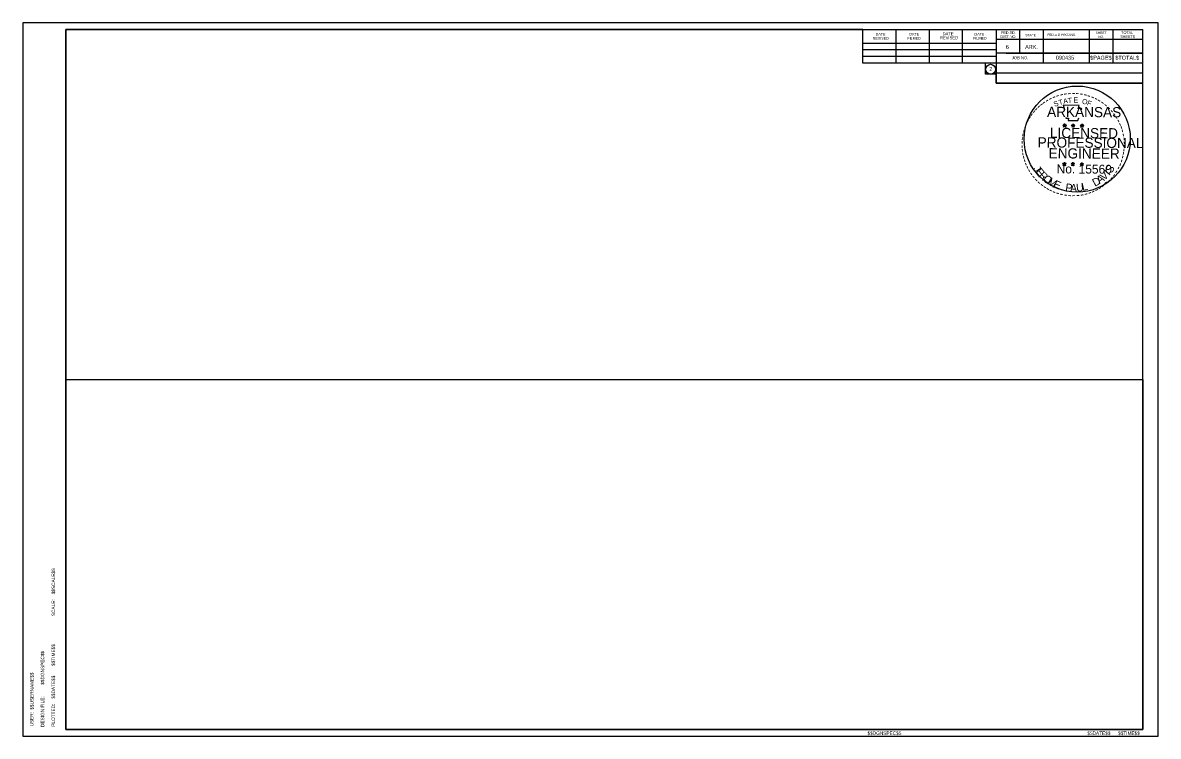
# Model space of a CAD drawing. Extents: x -1.3 to 32.1, y -0.2 to 20.7.
import ezdxf

# ---------------------------------------------------------------- set-up
doc = ezdxf.new("R2010")
doc.units = 0
for name, color, linetype in [('Level 24', 7, 'Continuous'), ('Level 37', 7, 'Continuous'), ('Level 49', 7, 'Continuous'), ('Level 62', 7, 'Continuous'), ('Level 63', 7, 'Continuous'), ('R_Border', 7, 'Continuous'), ('R_Border Notes', 7, 'Continuous'), ('Stamp Mask', 7, 'Continuous')]:
    doc.layers.add(name, color=color, linetype=linetype)

msp = doc.modelspace()

# ---------------------------------------------------------------- linework, layer by layer
at = {"layer": 'Level 24'}
for p, q in [((-0.001, 20.545), (-0.001, -0.001)), ((23.391, 19.557), (23.391, 20.545)), ((26.999, 19.557), (23.391, 19.557)), ((26.999, 19.232), (26.999, 19.557)), ((27.307, 19.233), (26.999, 19.232)), ((27.307, 18.973), (27.307, 19.233)), ((31.617, 18.973), (27.307, 18.973)), ((31.617, -0.001), (31.617, 18.973)), ((-0.001, -0.001), (31.617, -0.001))]:
    msp.add_line(p, q, dxfattribs=at)
msp.add_lwpolyline([(23.391, 20.545), (23.391, 20.545), (23.391, 20.545), (-0.001, 20.545)], dxfattribs=at)
at = {"layer": 'Level 37'}
for p, q in [((-0.002, 0.481), (-0.001, 10.271)), ((-0.001, 10.271), (31.617, 10.271)), ((31.617, 10.271), (31.617, -0.001)), ((-0.001, -0.001), (-0.002, 0.481)), ((-0.002, 0.481), (-0.002, 0.481)), ((31.617, -0.001), (-0.001, -0.001))]:
    msp.add_line(p, q, dxfattribs=at)
at = {"layer": 'Level 49'}
for p, q in [((29.266, 17.742), (29.319, 17.726)), ((29.266, 17.742), (29.304, 17.74)), ((29.266, 17.742), (29.304, 17.739)), ((29.266, 17.742), (29.301, 17.733)), ((29.266, 17.742), (29.301, 17.727)), ((29.266, 17.742), (29.301, 17.726)), ((29.266, 17.742), (29.301, 17.72)), ((29.288, 17.681), (29.319, 17.726)), ((29.288, 17.681), (29.301, 17.724)), ((29.288, 17.681), (29.304, 17.718)), ((29.288, 17.681), (29.306, 17.716)), ((29.288, 17.681), (29.312, 17.713)), ((29.288, 17.681), (29.319, 17.713)), ((29.288, 17.681), (29.319, 17.709)), ((29.319, 17.783), (29.312, 17.742)), ((29.319, 17.783), (29.312, 17.746)), ((29.319, 17.783), (29.315, 17.746)), ((29.319, 17.726), (29.319, 17.783)), ((29.319, 17.783), (29.328, 17.742)), ((29.319, 17.783), (29.326, 17.746)), ((29.319, 17.783), (29.321, 17.746)), ((29.371, 17.742), (29.319, 17.726)), ((29.35, 17.68), (29.319, 17.726)), ((29.35, 17.68), (29.319, 17.713)), ((29.35, 17.68), (29.319, 17.709)), ((29.371, 17.742), (29.323, 17.739)), ((29.35, 17.68), (29.323, 17.713)), ((29.371, 17.742), (29.328, 17.735)), ((29.371, 17.742), (29.328, 17.731)), ((29.35, 17.68), (29.328, 17.724)), ((29.35, 17.68), (29.328, 17.718)), ((29.35, 17.68), (29.334, 17.726)), ((29.371, 17.742), (29.336, 17.731)), ((29.371, 17.742), (29.341, 17.727)), ((29.371, 17.742), (29.343, 17.726)), ((29.514, 17.74), (29.568, 17.726)), ((29.514, 17.74), (29.553, 17.739)), ((29.514, 17.74), (29.553, 17.735)), ((29.514, 17.74), (29.553, 17.733)), ((29.514, 17.74), (29.551, 17.726)), ((29.514, 17.74), (29.551, 17.724)), ((29.514, 17.74), (29.551, 17.718)), ((29.536, 17.68), (29.568, 17.726)), ((29.536, 17.68), (29.553, 17.72)), ((29.536, 17.68), (29.553, 17.718)), ((29.536, 17.68), (29.555, 17.716)), ((29.536, 17.68), (29.56, 17.711)), ((29.536, 17.68), (29.568, 17.711)), ((29.536, 17.68), (29.568, 17.709)), ((29.568, 17.779), (29.56, 17.74)), ((29.568, 17.779), (29.56, 17.742)), ((29.568, 17.779), (29.562, 17.742)), ((29.568, 17.726), (29.568, 17.779)), ((29.568, 17.779), (29.577, 17.74)), ((29.568, 17.779), (29.575, 17.742)), ((29.568, 17.779), (29.57, 17.742)), ((29.619, 17.74), (29.568, 17.726)), ((29.599, 17.68), (29.568, 17.726)), ((29.599, 17.68), (29.568, 17.711)), ((29.599, 17.68), (29.568, 17.709)), ((29.619, 17.74), (29.573, 17.739)), ((29.599, 17.68), (29.573, 17.711)), ((29.619, 17.74), (29.577, 17.733)), ((29.619, 17.74), (29.577, 17.731)), ((29.599, 17.68), (29.577, 17.724)), ((29.599, 17.68), (29.577, 17.716)), ((29.599, 17.68), (29.583, 17.724)), ((29.619, 17.74), (29.584, 17.727)), ((29.619, 17.74), (29.59, 17.726)), ((29.619, 17.74), (29.592, 17.724)), ((29.778, 17.739), (29.831, 17.72)), ((29.778, 17.739), (29.82, 17.733)), ((29.778, 17.739), (29.816, 17.731)), ((29.778, 17.739), (29.816, 17.727)), ((29.778, 17.739), (29.815, 17.724)), ((29.778, 17.739), (29.815, 17.718)), ((29.778, 17.739), (29.815, 17.718)), ((29.798, 17.678), (29.831, 17.72)), ((29.798, 17.678), (29.816, 17.718)), ((29.798, 17.678), (29.82, 17.713)), ((29.798, 17.678), (29.82, 17.711)), ((29.798, 17.678), (29.831, 17.711)), ((29.798, 17.678), (29.828, 17.709)), ((29.798, 17.678), (29.835, 17.704)), ((29.831, 17.775), (29.822, 17.74)), ((29.831, 17.775), (29.828, 17.739)), ((29.831, 17.775), (29.828, 17.739)), ((29.831, 17.72), (29.831, 17.775)), ((29.831, 17.775), (29.842, 17.739)), ((29.831, 17.775), (29.839, 17.739)), ((29.831, 17.775), (29.835, 17.739)), ((29.883, 17.739), (29.831, 17.72)), ((29.861, 17.678), (29.831, 17.72)), ((29.861, 17.678), (29.831, 17.711)), ((29.861, 17.678), (29.831, 17.704)), ((29.883, 17.739), (29.837, 17.733)), ((29.861, 17.678), (29.837, 17.709)), ((29.883, 17.739), (29.842, 17.731)), ((29.883, 17.739), (29.842, 17.726)), ((29.861, 17.678), (29.842, 17.718)), ((29.861, 17.678), (29.842, 17.713)), ((29.861, 17.678), (29.846, 17.718)), ((29.883, 17.739), (29.85, 17.724)), ((29.883, 17.739), (29.851, 17.724)), ((29.883, 17.739), (29.857, 17.72)), ((29.258, 16.611), (29.312, 16.595)), ((29.258, 16.611), (29.297, 16.609)), ((29.258, 16.611), (29.295, 16.604)), ((29.258, 16.611), (29.295, 16.604)), ((29.258, 16.611), (29.295, 16.596)), ((29.258, 16.611), (29.295, 16.595)), ((29.258, 16.611), (29.295, 16.593)), ((29.277, 16.554), (29.312, 16.595)), ((29.277, 16.554), (29.295, 16.595)), ((29.277, 16.554), (29.297, 16.587)), ((29.277, 16.554), (29.299, 16.587)), ((29.277, 16.554), (29.312, 16.585)), ((29.277, 16.554), (29.304, 16.582)), ((29.277, 16.554), (29.312, 16.58)), ((29.312, 16.652), (29.301, 16.615)), ((29.312, 16.652), (29.304, 16.611)), ((29.312, 16.652), (29.306, 16.611)), ((29.341, 16.55), (29.308, 16.58)), ((29.312, 16.595), (29.312, 16.652)), ((29.312, 16.652), (29.319, 16.611)), ((29.312, 16.652), (29.319, 16.611)), ((29.312, 16.652), (29.312, 16.611)), ((29.363, 16.611), (29.312, 16.595)), ((29.341, 16.55), (29.312, 16.595)), ((29.341, 16.55), (29.312, 16.582)), ((29.341, 16.55), (29.314, 16.582)), ((29.363, 16.611), (29.315, 16.609)), ((29.363, 16.611), (29.319, 16.604)), ((29.363, 16.611), (29.319, 16.602)), ((29.341, 16.55), (29.319, 16.595)), ((29.341, 16.55), (29.319, 16.587)), ((29.363, 16.611), (29.326, 16.6)), ((29.341, 16.55), (29.326, 16.595)), ((29.363, 16.611), (29.33, 16.596)), ((29.363, 16.611), (29.334, 16.595)), ((29.507, 16.611), (29.56, 16.595)), ((29.507, 16.611), (29.546, 16.608)), ((29.507, 16.611), (29.546, 16.604)), ((29.507, 16.611), (29.546, 16.602)), ((29.507, 16.611), (29.544, 16.596)), ((29.507, 16.611), (29.544, 16.593)), ((29.507, 16.611), (29.544, 16.589)), ((29.525, 16.55), (29.56, 16.595)), ((29.525, 16.55), (29.546, 16.593)), ((29.525, 16.55), (29.546, 16.585)), ((29.525, 16.55), (29.548, 16.585)), ((29.525, 16.55), (29.553, 16.582)), ((29.525, 16.55), (29.56, 16.582)), ((29.525, 16.55), (29.56, 16.578)), ((29.56, 16.648), (29.551, 16.611)), ((29.56, 16.648), (29.553, 16.611)), ((29.56, 16.648), (29.555, 16.611)), ((29.59, 16.55), (29.559, 16.578)), ((29.56, 16.595), (29.56, 16.648)), ((29.56, 16.648), (29.568, 16.609)), ((29.56, 16.648), (29.568, 16.609)), ((29.56, 16.648), (29.56, 16.611)), ((29.61, 16.609), (29.56, 16.595)), ((29.59, 16.55), (29.56, 16.595)), ((29.59, 16.55), (29.56, 16.582)), ((29.59, 16.55), (29.562, 16.582)), ((29.61, 16.609), (29.566, 16.609)), ((29.61, 16.609), (29.568, 16.602)), ((29.61, 16.609), (29.568, 16.602)), ((29.59, 16.55), (29.568, 16.593)), ((29.59, 16.55), (29.568, 16.587)), ((29.61, 16.609), (29.575, 16.596)), ((29.59, 16.55), (29.575, 16.593)), ((29.61, 16.609), (29.581, 16.595)), ((29.61, 16.609), (29.583, 16.593)), ((29.77, 16.608), (29.824, 16.589)), ((29.77, 16.608), (29.809, 16.604)), ((29.77, 16.608), (29.809, 16.6)), ((29.77, 16.608), (29.807, 16.596)), ((29.77, 16.608), (29.807, 16.593)), ((29.77, 16.608), (29.805, 16.589)), ((29.77, 16.608), (29.805, 16.585)), ((29.791, 16.547), (29.824, 16.589)), ((29.791, 16.547), (29.807, 16.589)), ((29.791, 16.547), (29.809, 16.582)), ((29.791, 16.547), (29.813, 16.582)), ((29.791, 16.547), (29.816, 16.578)), ((29.791, 16.547), (29.822, 16.578)), ((29.791, 16.547), (29.824, 16.574)), ((29.824, 16.646), (29.815, 16.608)), ((29.824, 16.646), (29.816, 16.608)), ((29.824, 16.646), (29.82, 16.608)), ((29.853, 16.547), (29.822, 16.578)), ((29.853, 16.547), (29.822, 16.574)), ((29.824, 16.589), (29.824, 16.646)), ((29.824, 16.646), (29.831, 16.608)), ((29.824, 16.646), (29.831, 16.608)), ((29.824, 16.646), (29.824, 16.608)), ((29.875, 16.608), (29.824, 16.589)), ((29.853, 16.547), (29.824, 16.589)), ((29.853, 16.547), (29.828, 16.578)), ((29.875, 16.608), (29.829, 16.604)), ((29.875, 16.608), (29.831, 16.6)), ((29.875, 16.608), (29.831, 16.596)), ((29.853, 16.547), (29.831, 16.582)), ((29.853, 16.547), (29.835, 16.589)), ((29.853, 16.547), (29.837, 16.589)), ((29.875, 16.608), (29.842, 16.595)), ((29.875, 16.608), (29.844, 16.589)), ((29.875, 16.608), (29.846, 16.589))]:
    msp.add_line(p, q, dxfattribs=at)
for points in [[(29.277, 18.322), (29.314, 18.197)], [(29.8, 18.181), (29.822, 18.225), (29.717, 18.219), (29.741, 18.319), (29.277, 18.322)], [(29.319, 17.783), (29.35, 17.68), (29.266, 17.742), (29.371, 17.742), (29.288, 17.681), (29.319, 17.783)], [(29.349, 17.96), (29.349, 17.945), (29.431, 17.943), (29.424, 17.875), (29.702, 17.873), (29.732, 17.95)], [(29.568, 17.779), (29.599, 17.68), (29.514, 17.74), (29.619, 17.74), (29.536, 17.68), (29.568, 17.779)], [(29.831, 17.775), (29.861, 17.678), (29.778, 17.739), (29.883, 17.739), (29.798, 17.678), (29.831, 17.775)], [(29.312, 16.652), (29.341, 16.55), (29.258, 16.611), (29.363, 16.611), (29.277, 16.554), (29.312, 16.652)], [(29.56, 16.648), (29.59, 16.55), (29.507, 16.611), (29.61, 16.609), (29.525, 16.55), (29.56, 16.648)], [(29.824, 16.646), (29.853, 16.547), (29.77, 16.608), (29.875, 16.608), (29.791, 16.547), (29.824, 16.646)], [(30.515, 16.009), (30.507, 16.033), (30.551, 16.07)], [(30.548, 16.075), (30.555, 16.053), (30.511, 16.014)], [(30.555, 16.057), (30.511, 16.018)], [(30.555, 16.053), (30.513, 16.016)]]:
    msp.add_lwpolyline(points, dxfattribs=at)
for centre, radius in [((29.32, 17.725), 0.0257), ((29.32, 17.725), 0.0233), ((29.32, 17.725), 0.0216), ((29.32, 17.725), 0.0198), ((29.32, 17.725), 0.0173), ((29.32, 17.725), 0.016), ((29.32, 17.725), 0.0148), ((29.32, 17.725), 0.0127), ((29.32, 17.725), 0.0112), ((29.32, 17.725), 0.00927), ((29.32, 17.725), 0.00739), ((29.32, 17.725), 0.00551), ((29.32, 17.725), 0.00442), ((29.32, 17.725), 0.00215), ((29.569, 17.723), 0.0257), ((29.569, 17.723), 0.0233), ((29.569, 17.723), 0.0216), ((29.569, 17.723), 0.0198), ((29.569, 17.723), 0.0173), ((29.569, 17.723), 0.016), ((29.569, 17.723), 0.0148), ((29.569, 17.723), 0.0127), ((29.569, 17.723), 0.0112), ((29.569, 17.723), 0.00927), ((29.569, 17.723), 0.00739), ((29.569, 17.723), 0.00551), ((29.569, 17.723), 0.00442), ((29.569, 17.723), 0.00215), ((29.833, 17.719), 0.0257), ((29.833, 17.719), 0.0233), ((29.833, 17.719), 0.0216), ((29.833, 17.719), 0.0198), ((29.833, 17.719), 0.0173), ((29.833, 17.719), 0.016), ((29.833, 17.719), 0.0148), ((29.833, 17.719), 0.0127), ((29.833, 17.719), 0.0112), ((29.833, 17.719), 0.00927), ((29.833, 17.719), 0.00739), ((29.833, 17.719), 0.00551), ((29.833, 17.719), 0.00442), ((29.833, 17.719), 0.00215), ((29.312, 16.595), 0.0257), ((29.312, 16.595), 0.0233), ((29.312, 16.595), 0.0216), ((29.312, 16.595), 0.0198), ((29.312, 16.595), 0.0173), ((29.312, 16.595), 0.016), ((29.312, 16.595), 0.0148), ((29.312, 16.595), 0.0127), ((29.312, 16.595), 0.0112), ((29.312, 16.595), 0.00927), ((29.312, 16.595), 0.00739), ((29.312, 16.595), 0.00551), ((29.312, 16.595), 0.00442), ((29.312, 16.595), 0.00215), ((29.561, 16.593), 0.0257), ((29.561, 16.593), 0.0233), ((29.561, 16.593), 0.0216), ((29.561, 16.593), 0.0198), ((29.561, 16.593), 0.0173), ((29.561, 16.593), 0.016), ((29.561, 16.593), 0.0148), ((29.561, 16.593), 0.0127), ((29.561, 16.593), 0.0112), ((29.561, 16.593), 0.00927), ((29.561, 16.593), 0.00739), ((29.561, 16.593), 0.00551), ((29.561, 16.593), 0.00442), ((29.561, 16.593), 0.00215), ((29.824, 16.589), 0.0257), ((29.824, 16.589), 0.0233), ((29.824, 16.589), 0.0216), ((29.824, 16.589), 0.0198), ((29.824, 16.589), 0.0173), ((29.824, 16.589), 0.016), ((29.824, 16.589), 0.0148), ((29.824, 16.589), 0.0127), ((29.824, 16.589), 0.0112), ((29.824, 16.589), 0.00927), ((29.824, 16.589), 0.00739), ((29.824, 16.589), 0.00551), ((29.824, 16.589), 0.00442), ((29.824, 16.589), 0.00215)]:
    msp.add_circle(centre, radius, dxfattribs=at)
at = {"layer": 'Level 62'}
msp.add_lwpolyline([(-0.001, -0.001), (31.617, -0.001), (31.617, 19.265), (27.307, 19.265), (27.211, 19.232), (26.999, 19.232), (26.999, 19.557), (23.391, 19.557), (23.391, 20.545), (23.391, 20.545), (23.391, 20.545), (-0.001, 20.545)], close=True, dxfattribs=at)
at = {"layer": 'Level 63'}
msp.add_lwpolyline([(-1.263, -0.2), (32.067, -0.2), (32.067, 20.746), (-1.263, 20.746)], close=True, dxfattribs=at)
at = {"layer": 'R_Border'}
for p, q in [((-0.001, 20.545), (31.617, 20.545)), ((-0.001, -0.001), (-0.001, 20.545)), ((23.391, 19.557), (23.391, 20.545)), ((24.377, 19.557), (24.377, 20.525)), ((25.353, 19.557), (25.353, 20.525)), ((26.321, 19.557), (26.321, 20.525)), ((27.307, 20.545), (27.307, 18.973)), ((27.991, 20.545), (27.991, 19.851)), ((28.685, 20.545), (28.685, 19.557)), ((30.043, 20.545), (30.043, 19.557)), ((30.737, 20.545), (30.737, 19.557)), ((31.617, -0.001), (31.617, 20.545)), ((23.391, 20.143), (27.307, 20.143)), ((31.617, 20.251), (27.307, 20.251)), ((31.617, 20.253), (31.617, 20.253)), ((23.391, 19.957), (27.307, 19.957)), ((23.391, 19.557), (23.391, 19.763)), ((23.391, 19.763), (27.307, 19.763)), ((31.617, 19.851), (27.307, 19.851)), ((27.603, 19.851), (31.617, 19.851)), ((31.617, 19.557), (23.391, 19.557)), ((27.307, 18.973), (31.617, 18.973)), ((31.617, -0.001), (-0.001, -0.001))]:
    msp.add_line(p, q, dxfattribs=at)
msp.add_circle((27.146, 19.379), 0.147, dxfattribs=at)
at = {"layer": 'Stamp Mask'}
msp.add_circle((29.689, 17.331), 1.557, dxfattribs=at)

# ---------------------------------------------------------------- texts
at = {"layer": 'Level 49'}
for s, height, rotation, p in [('-', 0.239, 9.8217, (29.301, 18.553)), ('-', 0.239, 5.4992, (29.411, 18.567)), ('-', 0.239, 359.7886, (29.525, 18.578)), ('-', 0.239, 357.3454, (29.636, 18.575)), ('-', 0.239, 351.7641, (29.745, 18.566)), ('-', 0.239, 38.5531, (28.652, 18.238)), ('-', 0.239, 35.8341, (28.722, 18.295)), ('-', 0.239, 33.666, (28.809, 18.354)), ('-', 0.239, 28.3942, (28.899, 18.407)), ('-', 0.239, 23.9096, (28.993, 18.453)), ('S', 0.149, 21.1964, (29.028, 18.276)), ('-', 0.239, 18.7785, (29.089, 18.494)), ('T', 0.149, 16.006, (29.164, 18.326)), ('-', 0.239, 13.2326, (29.201, 18.529)), ('A', 0.149, 10.8156, (29.29, 18.363)), ('T', 0.149, 5.6252, (29.417, 18.387)), ('E', 0.149, 0.4347, (29.581, 18.402)), ('O', 0.149, 350.0539, (29.82, 18.37)), ('-', 0.239, 346.8073, (29.853, 18.549)), ('F', 0.149, 339.6731, (29.962, 18.333)), ('-', 0.239, 341.9386, (29.947, 18.523)), ('-', 0.239, 337.4575, (30.056, 18.49)), ('-', 0.239, 333.7235, (30.152, 18.451)), ('-', 0.239, 329.2433, (30.236, 18.407)), ('-', 0.239, 325.4651, (30.332, 18.35)), ('-', 0.239, 320.1321, (30.422, 18.287)), ('-', 0.239, 57.673, (28.347, 17.869)), ('-', 0.239, 53.8349, (28.394, 17.95)), ('-', 0.239, 50.2166, (28.457, 18.035)), ('-', 0.239, 48.0254, (28.518, 18.107)), ('-', 0.239, 42.5646, (28.586, 18.177)), ('ARKANSAS', 0.2985, 359.6024, (28.803, 17.983)), ('-', 0.239, 315.181, (30.513, 18.214)), ('-', 0.239, 309.4821, (30.596, 18.131)), ('-', 0.239, 306.2546, (30.671, 18.041)), ('-', 0.239, 71.9969, (28.227, 17.595)), ('-', 0.239, 67.3767, (28.262, 17.689)), ('-', 0.239, 62.4738, (28.3, 17.779)), ('LICENSED', 0.2985, 359.6024, (28.887, 17.365)), ('-', 0.209, 303.2777, (30.745, 17.954)), ('-', 0.239, 299.2708, (30.791, 17.864)), ('-', 0.239, 294.2652, (30.839, 17.772)), ('-', 0.239, 290.1752, (30.879, 17.689)), ('-', 0.239, 84.7887, (28.164, 17.28)), ('-', 0.239, 80.8037, (28.175, 17.383)), ('-', 0.239, 75.0634, (28.197, 17.488)), ('PROFESSIONAL', 0.29847, 359.6024, (28.525, 17.085)), ('-', 0.239, 284.7257, (30.911, 17.6)), ('-', 0.239, 280.1517, (30.94, 17.488)), ('-', 0.239, 276.1986, (30.966, 17.374)), ('-', 0.239, 93.7983, (28.164, 17.066)), ('-', 0.239, 88.6646, (28.16, 17.175)), ('-', 0.239, 98.5503, (28.175, 16.965)), ('ENGINEER', 0.2985, 359.6024, (28.848, 16.766)), ('-', 0.239, 263.1196, (30.973, 17.074)), ('-', 0.239, 273.9325, (30.973, 17.265)), ('-', 0.239, 269.5431, (30.977, 17.173)), ('-', 0.239, 101.3173, (28.192, 16.856)), ('-', 0.239, 105.0602, (28.218, 16.768)), ('-', 0.239, 108.6898, (28.249, 16.676)), ('-', 0.239, 252.4705, (30.918, 16.766)), ('-', 0.239, 255.365, (30.944, 16.875)), ('-', 0.239, 260.5977, (30.96, 16.976)), ('-', 0.239, 113.6667, (28.286, 16.584)), ('-', 0.239, 115.3313, (28.332, 16.491)), ('-', 0.239, 120.0495, (28.383, 16.403)), ('-', 0.239, 125.4958, (28.444, 16.32)), ('J', 0.23, 303.9209, (28.377, 16.456)), ('E', 0.23, 308.618, (28.442, 16.36)), ('R', 0.23, 314.7784, (28.538, 16.242)), ('No. 15560', 0.2626, 359.6024, (29.083, 16.324)), ('V', 0.23, 41.4844, (30.475, 16.1)), ('I', 0.23, 49.9999, (30.628, 16.244)), ('S', 0.23, 53.5227, (30.684, 16.31)), ('-', 0.239, 238.6736, (30.784, 16.462)), ('-', 0.239, 244.2221, (30.842, 16.573)), ('-', 0.239, 247.4911, (30.885, 16.665)), ('-', 0.239, 130.3205, (28.51, 16.237)), ('-', 0.239, 133.8262, (28.588, 16.156)), ('-', 0.239, 138.5362, (28.663, 16.086)), ('-', 0.239, 144.2487, (28.75, 16.025)), ('O', 0.23, 321.6761, (28.66, 16.124)), ('M', 0.23, 328.1357, (28.787, 16.027)), ('E', 0.23, 336.4966, (28.966, 15.924)), ('P', 0.23, 351.9783, (29.328, 15.805)), ('A', 0.23, 357.9896, (29.475, 15.786)), ('U', 0.23, 5.7635, (29.666, 15.785)), ('L', 0.23, 13.0992, (29.846, 15.807)), ('D', 0.23, 28.5809, (30.207, 15.928)), ('A', 0.23, 34.8903, (30.343, 16.004)), ('-', 0.239, 225.3677, (30.586, 16.197)), ('-', 0.239, 233.4476, (30.656, 16.283)), ('-', 0.239, 233.4476, (30.726, 16.364)), ('-', 0.239, 147.6922, (28.831, 15.968)), ('-', 0.239, 151.1728, (28.916, 15.92)), ('-', 0.239, 154.2026, (28.997, 15.882)), ('-', 0.239, 158.1636, (29.089, 15.841)), ('-', 0.239, 162.4007, (29.192, 15.81)), ('-', 0.239, 167.1579, (29.297, 15.786)), ('-', 0.239, 172.7179, (29.411, 15.769)), ('-', 0.239, 176.1207, (29.524, 15.758)), ('-', 0.239, 181.1942, (29.634, 15.762)), ('-', 0.239, 185.4191, (29.756, 15.771)), ('-', 0.239, 190.8882, (29.866, 15.79)), ('-', 0.239, 195.0767, (29.975, 15.819)), ('-', 0.239, 200.3208, (30.076, 15.856)), ('-', 0.239, 203.854, (30.168, 15.896)), ('-', 0.239, 206.9592, (30.262, 15.943)), ('-', 0.239, 211.8515, (30.345, 15.994)), ('-', 0.239, 215.3387, (30.424, 16.051))]:
    msp.add_text(s, height=height, rotation=rotation, dxfattribs=at).set_placement(p)
at = {"layer": 'R_Border'}
for s, height, p in [('DATE', 0.0782, (23.771, 20.369)), ('DATE', 0.0782, (24.757, 20.369)), ('REVISED', 0.0879, (25.657, 20.261)), ('DATE', 0.0879, (25.735, 20.379)), ('DATE', 0.0782, (26.673, 20.369)), ('DIST.NO.', 0.0782, (27.435, 20.299)), ('FED.RD.', 0.0782, (27.455, 20.417)), ('STATE', 0.0684, (28.167, 20.349)), ('FED.AID PROJ.NO.', 0.0684, (28.813, 20.359)), ('SHEET', 0.0684, (30.229, 20.417)), ('NO.', 0.0684, (30.307, 20.299)), ('SHEETS', 0.0782, (30.953, 20.299)), ('TOTAL', 0.0782, (30.981, 20.417)), ('REVISED', 0.0782, (23.683, 20.251)), ('FILMED', 0.0782, (24.699, 20.251)), ('FILMED', 0.0782, (26.633, 20.251)), ('6', 0.117, (27.591, 19.977)), ('ARK.', 0.1172, (28.157, 19.977)), ('JOB NO.', 0.0879, (27.767, 19.675)), ('090435', 0.1172, (29.06, 19.66)), ('$PAGE$', 0.1172, (30.067, 19.66)), ('$TOTAL$', 0.1172, (30.806, 19.66)), ('2', 0.117, (27.108, 19.329))]:
    msp.add_text(s, height=height, dxfattribs=at).set_placement(p)
at = {"layer": 'R_Border Notes'}
for s, p in [('$$SCALE$$', (-0.313, 3.969)), ('SCALE:', (-0.313, 3.328)), ('$$TIME$$', (-0.316, 1.867)), ('$$DGNSPEC$$', (-0.632, 1.314)), ('$$USERNAME$$', (-0.944, 0.58)), ('$$DATE$$', (-0.316, 0.903)), ('DESIGN FILE:', (-0.632, 0.073)), ('PLOTTED:', (-0.316, 0.081)), ('USER:', (-0.948, 0.089))]:
    msp.add_text(s, height=0.1, rotation=90, dxfattribs=at).set_placement(p)
for s, p in [('$$DGNSPEC$$', (23.534, -0.159)), ('$$DATE$$', (29.986, -0.159)), ('$$TIME$$', (30.887, -0.159))]:
    msp.add_text(s, height=0.1, dxfattribs=at).set_placement(p)

doc.saveas('drawing.dxf')
